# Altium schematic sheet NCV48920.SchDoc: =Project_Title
size A4
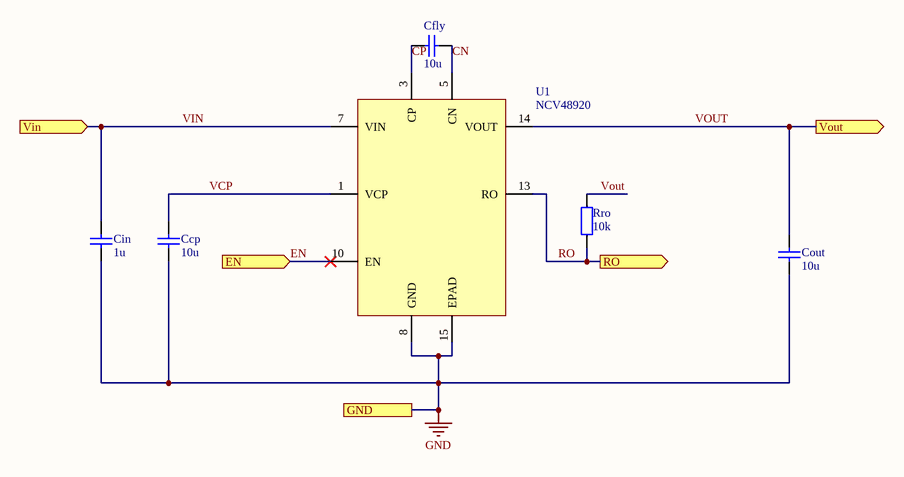
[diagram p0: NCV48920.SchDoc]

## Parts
Ccp  value 10u  [0805_CAP_MAX]  (hidden comment: GCM21BR71A106KE22K)
Cfly  value 10u  [0805_CAP_MAX]  (hidden comment: GCM21BR71A106KE22K)
Cin  value 1u  [0805_CAP_MAX]  (hidden comment: GCM21BR71A106KE22K)
Cout  value 10u  [0805_CAP_MAX]  (hidden comment: GCM21BR71A106KE22K)
Rro  value 10k  [0603_RES]  (hidden comment: RC0402FR-07100KL)
U1  NCV48920  [TSSOP-14-EP]

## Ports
EN (in), GND, RO (out), Vin (in), Vout (out)

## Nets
GND: Ccp.2 Cin.2 Cout.2 U1.8(GND) U1.15(EPAD) ; port GND
CN: Cfly.2 U1.5(CN)
CP: Cfly.1 U1.3(CP)
EN: U1.10(EN) ; port EN
RO: Rro.2 U1.13(RO) ; port RO
VCP: Ccp.1 U1.1(VCP)
VIN: Cin.1 U1.7(VIN) ; port Vin
VOUT: Cout.1 Rro.1 U1.14(VOUT) ; port Vout

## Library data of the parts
Ccp Cfly Cout = GCM21BR71A106KE22K: 10uF; 10V; X7R; 10%; 0805; GCM21BR71A106KE22K; Murata; Signature Author: Hukel; Substitution Allowed: Yes; Value/Rating: 10u/10V
Cin = GCM21BR71A106KE22K: 10uF; 10V; X7R; 10%; 0805; GCM21BR71A106KE22K; Murata; Signature Author: Hukel; Substitution Allowed: Yes; Value/Rating: 1u/10V
Rro = 100k_0402_1%: 100k; 1/16W; 1%; 0402; Yageo; Signature Author: Hukel; Value/Rating: 10k/1/16W; Substitution Allowed: Yes
U1 = NCV48920: 600 mA Buck/ 300 mA Noost Charge Pump Regulator for Automotive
